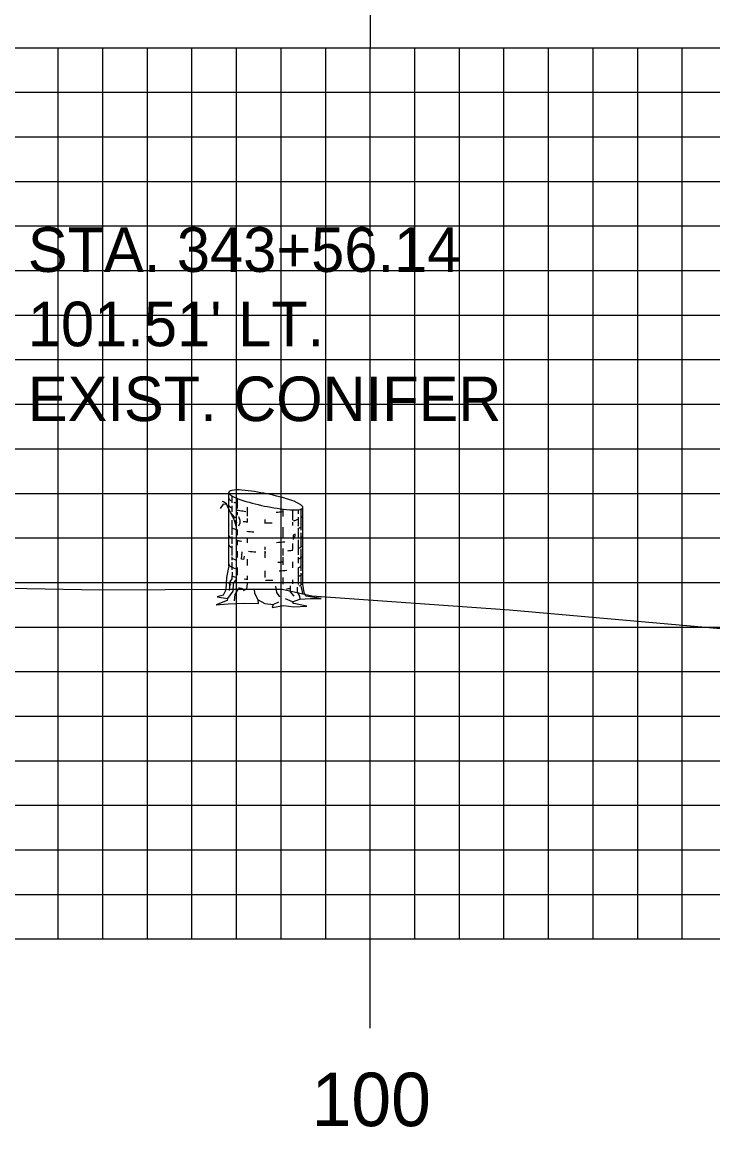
# Model space of a CAD drawing. Extents: x 1825147 to 1825490, y 442591 to 442811.
# Drawn here: x 1825204.55 to 1825220.05, y 442764.45 to 442789.24 of the extents above; entities that cross this region are included whole.
import ezdxf

# ---------------------------------------------------------------- set-up
doc = ezdxf.new("R2010")
doc.units = 0
for name, color, linetype in [('D_Text_Monospaced', 7, 'Continuous'), ('H_V ANNOTATION', 7, 'Continuous'), ('M_Trees_Conifer_Pay', 7, 'Continuous'), ('MAJOR', 7, 'Continuous'), ('MINOR', 7, 'Continuous'), ('S_Roadway_Centerline', 7, 'Continuous')]:
    doc.layers.add(name, color=color, linetype=linetype)

msp = doc.modelspace()

# ---------------------------------------------------------------- linework, layer by layer
at = {"layer": 'M_Trees_Conifer_Pay'}
for p, q in [((1825209.186, 442777.037), (1825209.186, 442778.684)), ((1825209.257, 442778.612), (1825209.257, 442778.45)), ((1825209.375, 442778.551), (1825209.375, 442778.328)), ((1825209.257, 442778.382), (1825209.257, 442778.254)), ((1825209.375, 442778.24), (1825209.375, 442778.192)), ((1825209.603, 442778.355), (1825209.603, 442778.156)), ((1825210.399, 442778.313), (1825210.399, 442778.145)), ((1825210.619, 442778.293), (1825210.619, 442778.06)), ((1825210.744, 442778.301), (1825210.744, 442778.203)), ((1825210.802, 442778.312), (1825210.802, 442777.841)), ((1825210.85, 442776.627), (1825210.85, 442778.349)), ((1825209.257, 442778.067), (1825209.257, 442777.731)), ((1825209.317, 442778.057), (1825209.369, 442777.997)), ((1825209.603, 442778.098), (1825209.603, 442778.009)), ((1825209.993, 442778.081), (1825209.993, 442777.986)), ((1825210.619, 442778.02), (1825210.619, 442777.946)), ((1825210.744, 442778.129), (1825210.744, 442777.925)), ((1825209.375, 442777.857), (1825209.375, 442777.725)), ((1825210.399, 442777.908), (1825210.399, 442777.671)), ((1825210.744, 442777.867), (1825210.744, 442777.667)), ((1825210.802, 442777.776), (1825210.802, 442777.468)), ((1825209.257, 442777.694), (1825209.257, 442777.532)), ((1825209.257, 442777.484), (1825209.257, 442777.268)), ((1825209.375, 442777.614), (1825209.375, 442777.505)), ((1825209.603, 442777.662), (1825209.603, 442777.557)), ((1825210.619, 442777.542), (1825210.619, 442777.404)), ((1825210.744, 442777.62), (1825210.744, 442777.284)), ((1825209.257, 442777.237), (1825209.257, 442777.163)), ((1825209.375, 442777.369), (1825209.375, 442777.227)), ((1825209.993, 442777.468), (1825209.993, 442777.394)), ((1825209.993, 442777.369), (1825209.993, 442777.221)), ((1825210.399, 442777.427), (1825210.399, 442777.274)), ((1825210.399, 442777.231), (1825210.399, 442777.058)), ((1825210.744, 442777.231), (1825210.744, 442777.095)), ((1825210.802, 442777.421), (1825210.802, 442776.929)), ((1825209.257, 442777.122), (1825209.257, 442776.949)), ((1825209.375, 442777), (1825209.375, 442776.828)), ((1825209.603, 442777.19), (1825209.603, 442777.043)), ((1825210.619, 442777.132), (1825210.619, 442776.99)), ((1825210.744, 442776.996), (1825210.744, 442776.618)), ((1825209.603, 442776.811), (1825209.603, 442776.723)), ((1825209.993, 442776.929), (1825209.993, 442776.776)), ((1825210.399, 442776.78), (1825210.399, 442776.627)), ((1825210.619, 442776.728), (1825210.619, 442776.634)), ((1825210.802, 442776.875), (1825210.802, 442776.627)), ((1825210.182, 442776.17), (1825210.308, 442776.234)), ((1825210.619, 442776.234), (1825210.456, 442776.298))]:
    msp.add_line(p, q, dxfattribs=at)
for points in [[(1825209.369, 442778.182), (1825209.332, 442778.108), (1825209.285, 442778.165), (1825209.227, 442778.234), (1825209.134, 442778.427), (1825209.07, 442778.474), (1825209.039, 442778.481)], [(1825209.14, 442778.415), (1825209.064, 442778.423), (1825208.992, 442778.324)], [(1825209.354, 442777.929), (1825209.317, 442778.057), (1825209.254, 442778.172), (1825209.223, 442778.24), (1825209.154, 442778.386)], [(1825209.402, 442778.145), (1825209.433, 442778.06), (1825209.437, 442777.993), (1825209.406, 442777.929)], [(1825210.671, 442777.655), (1825210.676, 442777.75), (1825210.633, 442777.727), (1825210.633, 442777.633)], [(1825209.531, 442777.256), (1825209.519, 442777.179), (1825209.472, 442777.19), (1825209.484, 442777.356)], [(1825209.186, 442777.037), (1825209.134, 442776.776), (1825209.118, 442776.502), (1825209.06, 442776.377), (1825208.924, 442776.346), (1825209.155, 442776.308), (1825209.155, 442776.308), (1825209.149, 442776.261), (1825208.901, 442776.167), (1825209.176, 442776.183), (1825209.531, 442776.203), (1825209.853, 442776.193), (1825209.846, 442776.276), (1825209.995, 442776.193), (1825210.182, 442776.17), (1825210.157, 442776.102), (1825210.425, 442776.146), (1825210.646, 442776.119), (1825210.938, 442776.136), (1825210.65, 442776.193), (1825210.619, 442776.234), (1825210.781, 442776.292), (1825211.018, 442776.303), (1825211.259, 442776.303), (1825210.917, 442776.36), (1825210.876, 442776.44), (1825210.85, 442776.627)], [(1825209.359, 442776.749), (1825209.285, 442776.644), (1825209.28, 442776.471), (1825209.155, 442776.308)], [(1825209.26, 442776.895), (1825209.254, 442776.749), (1825209.207, 442776.681), (1825209.196, 442776.482)], [(1825209.317, 442776.255), (1825209.332, 442776.393), (1825209.406, 442776.522)], [(1825209.596, 442776.644), (1825209.585, 442776.518), (1825209.511, 442776.475)], [(1825209.846, 442776.276), (1825209.772, 442776.417), (1825209.762, 442776.518)], [(1825210.335, 442776.346), (1825210.267, 442776.44), (1825210.24, 442776.58)], [(1825210.561, 442776.587), (1825210.561, 442776.455), (1825210.65, 442776.356)], [(1825210.724, 442776.56), (1825210.718, 442776.444), (1825210.771, 442776.356), (1825210.781, 442776.292)], [(1825210.802, 442776.58), (1825210.823, 442776.502), (1825210.843, 442776.408)]]:
    msp.add_lwpolyline(points, dxfattribs=at)
for centre, radius, start, end in [((1825209.246, 442778.641), 0.0817, 108.9499, 123.2806), ((1825209.301, 442778.481), 0.251, 100.7806, 108.9499), ((1825209.404, 442777.94), 0.802, 84.6206, 100.7806), ((1825208.994, 442773.582), 5.179, 78.2806, 84.6206), ((1825209.208, 442778.685), 0.0226, 156.5926, 168.2806), ((1825209.208, 442778.685), 0.0226, 168.2806, 179.9685), ((1825209.212, 442778.685), 0.0264, 179.9685, 190.7806), ((1825209.217, 442778.686), 0.0314, 190.7806, 203.4842), ((1825209.219, 442778.558), 0.0334, 185.7849, 196.0515), ((1825209.212, 442778.683), 0.0264, 145.7806, 156.5926), ((1825209.229, 442778.561), 0.0441, 196.0515, 210), ((1825209.236, 442778.694), 0.0527, 203.4842, 213.2806), ((1825209.216, 442778.68), 0.0314, 133.077, 145.7806), ((1825209.245, 442778.57), 0.0624, 210, 228.7494), ((1825209.261, 442778.71), 0.0817, 213.2806, 227.6113), ((1825209.23, 442778.665), 0.0527, 123.2806, 133.077), ((1825209.317, 442778.653), 0.172, 228.7494, 240), ((1825209.374, 442778.835), 0.251, 227.6113, 235.7806), ((1825209.684, 442779.29), 0.802, 235.7806, 251.9406), ((1825209.517, 442778.998), 0.571, 247.5868, 255.5683), ((1825211.041, 442783.452), 5.179, 251.9406, 258.2806), ((1825208.994, 442773.582), 5.179, 71.9406, 78.2806), ((1825210.351, 442777.743), 0.802, 55.7806, 71.9406), ((1825209.219, 442778.404), 0.0334, 185.7849, 196.0515), ((1825209.229, 442778.407), 0.0441, 196.0515, 210), ((1825209.245, 442778.416), 0.0624, 210, 228.7494), ((1825209.317, 442778.499), 0.172, 228.7494, 240), ((1825209.517, 442778.844), 0.571, 240, 242.9763), ((1825209.517, 442778.844), 0.571, 255.6333, 261.8968), ((1825210.017, 442782.361), 4.124, 261.8968, 263.762), ((1825211.041, 442783.452), 5.179, 258.2806, 264.6206), ((1825210.017, 442782.361), 4.124, 273.2669, 275.3045), ((1825210.631, 442779.094), 0.802, 264.6206, 280.7806), ((1825210.734, 442778.553), 0.251, 280.7806, 288.9499), ((1825210.661, 442778.199), 0.251, 47.6113, 55.7806), ((1825210.789, 442778.393), 0.0817, 288.9499, 303.2806), ((1825210.774, 442778.324), 0.0817, 33.2806, 47.6113), ((1825210.805, 442778.369), 0.0527, 303.2806, 313.077), ((1825210.819, 442778.353), 0.0314, 313.077, 325.7806), ((1825210.799, 442778.339), 0.0527, 23.4842, 33.2806), ((1825210.823, 442778.35), 0.0264, 325.7806, 336.5926), ((1825210.818, 442778.348), 0.0314, 10.7806, 23.4842), ((1825210.827, 442778.349), 0.0226, 336.5926, 348.2806), ((1825210.823, 442778.349), 0.0264, 359.9685, 10.7806), ((1825210.827, 442778.349), 0.0226, 348.2806, 359.9685), ((1825210.019, 442782.128), 4.124, 262.9442, 264.2151), ((1825210.019, 442782.128), 4.124, 269.6419, 270), ((1825210.019, 442782.128), 4.124, 270, 271.9249), ((1825210.52, 442778.611), 0.571, 282.0154, 293.1403), ((1825210.52, 442778.611), 0.571, 299.6633, 300), ((1825210.719, 442778.266), 0.172, 300, 311.2506), ((1825210.791, 442778.183), 0.0624, 311.2506, 330), ((1825210.807, 442778.174), 0.0441, 330, 343.9485), ((1825210.817, 442778.171), 0.0334, 0, 16.0515), ((1825210.817, 442778.171), 0.0334, 343.9485, 360), ((1825209.219, 442777.96), 0.0334, 185.7849, 196.0515), ((1825209.22, 442777.724), 0.0334, 185.7849, 196.0515), ((1825209.517, 442778.4), 0.571, 242.9571, 255.5507), ((1825210.018, 442781.917), 4.124, 264.0496, 266.2948), ((1825210.518, 442778.4), 0.571, 292.9413, 300), ((1825210.817, 442777.724), 0.0334, 0, 16.0515), ((1825210.817, 442777.724), 0.0334, 343.9485, 360), ((1825209.22, 442777.514), 0.0334, 185.7849, 196.0515), ((1825209.231, 442777.727), 0.0441, 196.0515, 210), ((1825209.231, 442777.517), 0.0441, 196.0515, 210), ((1825209.246, 442777.736), 0.0624, 210, 228.7494), ((1825209.246, 442777.526), 0.0624, 210, 228.7494), ((1825209.319, 442777.819), 0.172, 228.7494, 240), ((1825209.319, 442777.609), 0.172, 228.7494, 240), ((1825209.518, 442778.164), 0.571, 240, 242.8104), ((1825209.518, 442778.164), 0.571, 253.0704, 261.8968), ((1825210.019, 442781.681), 4.124, 261.8968, 262.3875), ((1825210.019, 442781.681), 4.124, 273.3324, 275.919), ((1825210.52, 442778.164), 0.571, 299.6633, 300), ((1825210.719, 442777.819), 0.172, 300, 311.2506), ((1825210.719, 442777.609), 0.172, 300, 311.2506), ((1825210.791, 442777.736), 0.0624, 311.2506, 330), ((1825210.791, 442777.526), 0.0624, 311.2506, 330), ((1825210.807, 442777.727), 0.0441, 330, 343.9485), ((1825210.807, 442777.517), 0.0441, 330, 343.9485), ((1825210.817, 442777.514), 0.0334, 0, 16.0515), ((1825210.817, 442777.514), 0.0334, 343.9485, 360), ((1825209.518, 442777.954), 0.571, 240, 242.8104), ((1825210.019, 442781.471), 4.124, 264.5431, 266.8507), ((1825210.019, 442781.471), 4.124, 269.6419, 270), ((1825210.019, 442781.471), 4.124, 276.8526, 278.1032), ((1825210.52, 442777.954), 0.571, 278.1032, 280.7293), ((1825210.52, 442777.954), 0.571, 293.1403, 300), ((1825210.719, 442777.372), 0.172, 300, 311.2506), ((1825210.791, 442777.289), 0.0624, 311.2506, 330), ((1825210.807, 442777.28), 0.0441, 330, 343.9485), ((1825210.817, 442777.277), 0.0334, 0, 16.0515), ((1825210.817, 442777.277), 0.0334, 343.9485, 360), ((1825209.22, 442777.08), 0.0334, 185.7849, 196.0515), ((1825209.231, 442777.083), 0.0441, 196.0515, 210), ((1825209.246, 442777.092), 0.0624, 210, 228.7494), ((1825209.319, 442777.174), 0.172, 228.7494, 240), ((1825209.518, 442777.519), 0.571, 240, 250.7093), ((1825209.518, 442777.717), 0.571, 242.8104, 254.6017), ((1825210.019, 442781.235), 4.124, 273.6807, 275.284), ((1825210.52, 442777.717), 0.571, 293.1403, 300), ((1825210.53, 442777.525), 0.571, 291.9732, 298.7631), ((1825210.817, 442777.08), 0.0334, 0, 16.0515), ((1825209.518, 442777.324), 0.571, 242.7279, 251.4933), ((1825210.019, 442780.841), 4.124, 263.2104, 264.2151), ((1825210.019, 442781.037), 4.124, 274.1603, 276.5009), ((1825210.52, 442777.324), 0.571, 293.1403, 300), ((1825210.719, 442776.979), 0.172, 300, 311.2506), ((1825210.791, 442776.896), 0.0624, 311.2506, 330), ((1825210.807, 442776.887), 0.0441, 330, 343.9485), ((1825210.817, 442776.884), 0.0334, 0, 16.0515), ((1825210.817, 442776.884), 0.0334, 343.9485, 360), ((1825209.22, 442776.664), 0.0334, 185.7849, 196.0515), ((1825209.231, 442776.667), 0.0441, 196.0515, 210), ((1825209.246, 442776.676), 0.0624, 210, 228.7494), ((1825209.319, 442776.758), 0.172, 228.7494, 240), ((1825209.518, 442777.104), 0.571, 258.363, 261.8968), ((1825210.019, 442780.621), 4.124, 261.8968, 262.6316), ((1825210.019, 442780.841), 4.124, 269.8672, 270), ((1825210.019, 442780.841), 4.124, 270, 272.1883), ((1825210.019, 442780.621), 4.124, 276.488, 277.5562), ((1825210.52, 442777.104), 0.571, 295.4686, 300), ((1825210.719, 442776.758), 0.172, 300, 311.2506), ((1825210.791, 442776.676), 0.0624, 311.2506, 330), ((1825210.807, 442776.667), 0.0441, 330, 343.9485), ((1825210.817, 442776.664), 0.0334, 0, 16.0515), ((1825210.817, 442776.664), 0.0334, 343.9485, 360)]:
    msp.add_arc(centre, radius, start, end, dxfattribs=at)
at = {"layer": 'MAJOR'}
for p, q in [((1825212.361, 442790.669), (1825212.361, 442788.665)), ((1825172.361, 442788.665), (1825452.361, 442788.665)), ((1825172.361, 442788.665), (1825452.361, 442788.665)), ((1825212.361, 442768.665), (1825212.361, 442788.665)), ((1825172.361, 442783.665), (1825452.361, 442783.665)), ((1825172.361, 442778.665), (1825452.361, 442778.665)), ((1825172.361, 442773.665), (1825452.361, 442773.665)), ((1825172.361, 442768.665), (1825452.361, 442768.665)), ((1825172.361, 442768.665), (1825452.361, 442768.665)), ((1825212.361, 442766.661), (1825212.361, 442768.665))]:
    msp.add_line(p, q, dxfattribs=at)
at = {"layer": 'MINOR'}
for p, q in [((1825205.361, 442768.665), (1825205.361, 442788.665)), ((1825206.361, 442768.665), (1825206.361, 442788.665)), ((1825207.361, 442768.665), (1825207.361, 442788.665)), ((1825208.361, 442768.665), (1825208.361, 442788.665)), ((1825209.361, 442768.665), (1825209.361, 442788.665)), ((1825210.361, 442768.665), (1825210.361, 442788.665)), ((1825211.361, 442768.665), (1825211.361, 442788.665)), ((1825213.361, 442768.665), (1825213.361, 442788.665)), ((1825214.361, 442768.665), (1825214.361, 442788.665)), ((1825215.361, 442768.665), (1825215.361, 442788.665)), ((1825216.361, 442768.665), (1825216.361, 442788.665)), ((1825217.361, 442768.665), (1825217.361, 442788.665)), ((1825218.361, 442768.665), (1825218.361, 442788.665)), ((1825219.361, 442768.665), (1825219.361, 442788.665)), ((1825172.361, 442787.665), (1825452.361, 442787.665)), ((1825172.361, 442786.665), (1825452.361, 442786.665)), ((1825172.361, 442785.665), (1825452.361, 442785.665)), ((1825172.361, 442784.665), (1825452.361, 442784.665)), ((1825172.361, 442782.665), (1825452.361, 442782.665)), ((1825172.361, 442781.665), (1825452.361, 442781.665)), ((1825172.361, 442780.665), (1825452.361, 442780.665)), ((1825172.361, 442779.665), (1825452.361, 442779.665)), ((1825172.361, 442777.665), (1825452.361, 442777.665)), ((1825172.361, 442776.665), (1825452.361, 442776.665)), ((1825172.361, 442775.665), (1825452.361, 442775.665)), ((1825172.361, 442774.665), (1825452.361, 442774.665)), ((1825172.361, 442772.665), (1825452.361, 442772.665)), ((1825172.361, 442771.665), (1825452.361, 442771.665)), ((1825172.361, 442770.665), (1825452.361, 442770.665)), ((1825172.361, 442769.665), (1825452.361, 442769.665))]:
    msp.add_line(p, q, dxfattribs=at)
at = {"layer": 'S_Roadway_Centerline'}
msp.add_lwpolyline([(1825200.366, 442776.551), (1825204.657, 442776.532), (1825206.293, 442776.503), (1825209.222, 442776.516), (1825210.383, 442776.517), (1825211.047, 442776.362), (1825215.483, 442776.048), (1825221.234, 442775.545), (1825224.236, 442775.276), (1825224.639, 442775.252), (1825226.531, 442775.134), (1825227.676, 442775.072), (1825228.368, 442775.05), (1825233.027, 442775.026), (1825236.221, 442775.027), (1825236.992, 442775.01), (1825240.062, 442774.843), (1825242.28, 442774.783), (1825243.751, 442774.801), (1825250.644, 442775.072), (1825260.365, 442775.484), (1825261.114, 442775.451), (1825271.443, 442775.535)], dxfattribs=at)

# ---------------------------------------------------------------- texts
at = {"layer": 'D_Text_Monospaced'}
for s, p in [('STA. 343+56.14', (1825204.679, 442783.634)), ("101.51' LT.", (1825204.679, 442781.966)), ('EXIST. CONIFER', (1825204.679, 442780.286))]:
    msp.add_text(s, height=0.99996, dxfattribs=at).set_placement(p)
at = {"layer": 'H_V ANNOTATION'}
msp.add_text('100', height=1.2, dxfattribs=at).set_placement((1825211.044, 442764.465))

doc.saveas('drawing.dxf')
